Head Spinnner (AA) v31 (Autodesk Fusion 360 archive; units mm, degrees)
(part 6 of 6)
sketch "Seperator Shape" plane through (0, 0, 0) normal (1, 0, 0) x axis (0, 1, 0)
  line L1 (-26.9, 11.1645) -> (-26.9, 1.7)
  line L2 (-26.9, 13) -> (-26.9, 11.1645)
  line L3 (-26.9, 14.7) -> (-26.9, 13)
  line L4 (-26.9, 13) -> (-26.9, 14.7)
  line L5 (-26.9, 11.1645) -> (-26.9, 13)
  line L6 (-26.9, 1.7) -> (-26.9, 11.1645)
  line L7 (26.9, 1.7) -> (-26.9, 1.7)
  line L8 (-26.9, 1.7) -> (26.9, 1.7)
  line L9 (26.9, 11.1645) -> (26.9, 13)
  line L10 (26.9, 1.7) -> (26.9, 11.1645)
  line L11 (26.9, 11.1645) -> (26.9, 1.7)
  line L12 (26.9, 11.1645) -> (26.9, 13)
  line L13 (26.9, 14.7) -> (26.9, 13)
  line L14 (26.9, 13) -> (26.9, 14.7)
  line L15 (-19, 7.7) -> (-26.9, 14.7)
  line L16 (19, 7.7) -> (-19, 7.7)
  line L17 (26.9, 14.7) -> (19, 7.7)
  line L18 (0, 7.7) -> (0, 1.7)
  point P5 (-26.9, 14.7)
  point P12 (-26.9, 14.7)
  point P11 (26.9, 14.7)
  point P15 (26.9, 14.7)
  point P16 (0, 1.7)
  point P17 (0, 7.7)
  point P13 (-19, 7.7)
  point P14 (19, 7.7)
  coincident P5 P12
  perpendicular L3 L16
  coincident P11 P15
  equal L15 L17
  midpoint L8 P16
  midpoint L16 P17
  dimension "d17" distance L7 L16 = 6
  dimension "d18" distance P13 P14 = 38
extrude "Extrude3" new body sketch "Seperator Shape" profile of L1 L2 L3 L4 L5 L6 L7 L8 L9 L10 L11 L12 L13 L14 L15 L16 L17 distance 0.625 (= "( 1.25 / 2 ) * 1 mm")
copy_paste_bodies "CopyPasteBodies1"
move "Move1"
copy_paste_bodies "CopyPasteBodies2"
move "Move2"
combine "Combine1"
fillet "Fillet3" ChordLen 1.5
fillet "Fillet5" ChordLen 2.056
sketch "Mounting Holes" plane through (0, 0, 0) normal (0, 0, -1) x axis (1, 0, 0)
  curve K1 (28.8789, -27.5393) -> (29.9393, -26.4789)
  line L1 (29.9393, -26.4789) -> (29.9393, 26.4789)
  curve K2 (29.9393, 26.4789) -> (28.8789, 27.5393)
  line L2 (28.8789, 27.5393) -> (-28.8789, 27.5393)
  curve K3 (-28.8789, 27.5393) -> (-29.9393, 26.4789)
  line L3 (-29.9393, 26.4789) -> (-29.9393, -26.4789)
  curve K4 (-29.9393, -26.4789) -> (-28.8789, -27.5393)
  line L4 (-28.8789, -27.5393) -> (28.8789, -27.5393)
  line L5 (-15.9, -26.9) -> (-15.9, 26.9)
  line L6 (-29.3, -26.9) -> (-15.9, -26.9)
  line L7 (-29.3, 26.9) -> (-29.3, -26.9)
  line L8 (-15.9, 26.9) -> (-29.3, 26.9)
  line L9 (-14.65, 26.9) -> (-14.65, -26.9)
  line L10 (-0.625, 26.9) -> (-14.65, 26.9)
  line L11 (-0.625, -26.9) -> (-0.625, 26.9)
  line L12 (-14.65, -26.9) -> (-0.625, -26.9)
  line L13 (0.625, 26.9) -> (0.625, -26.9)
  line L14 (14.65, 26.9) -> (0.625, 26.9)
  line L15 (14.65, -26.9) -> (14.65, 26.9)
  line L16 (0.625, -26.9) -> (14.65, -26.9)
  line L17 (15.9, 26.9) -> (15.9, -26.9)
  line L18 (29.3, 26.9) -> (15.9, 26.9)
  line L19 (29.3, -26.9) -> (29.3, 26.9)
  line L20 (15.9, -26.9) -> (29.3, -26.9)
  line L21 (15.9, 0.053) -> (29.3, 0)
  line L22 (14.65, 0) -> (15.9, 0.053)
  line L23 (0.625, 0) -> (14.65, 0)
  line L24 (-29.3, 0) -> (-15.9, 0)
  line L25 (-0.625, 0) -> (0.625, 0)
  line L26 (-15.9, 0) -> (-14.65, 0)
  line L27 (-14.65, 0) -> (-0.625, 0)
  circle C1 centre (22.6, 0.0265) radius 1.5
  circle C2 centre (7.6375, 0) radius 1.5
  circle C3 centre (-7.6375, 0) radius 1.5
  circle C4 centre (-22.6, 0) radius 1.5
  point P26 (29.3, 0)
  point P27 (-29.3, 0)
  point P28 (15.9, 0.053)
  point P29 (14.65, 0)
  point P30 (0.625, 0)
  point P31 (-15.9, 0)
  point P32 (-0.625, 0)
  point P33 (-14.65, 0)
  point P34 (22.6, 0.0265)
  point P35 (7.6375, 0)
  point P36 (-7.6375, 0)
  point P37 (-22.6, 0)
  point P38 (22.6, 0.0265)
  point P39 (7.6375, 0)
  point P40 (-7.6375, 0)
  point P41 (-22.6, 0)
  midpoint L19 P26
  midpoint L7 P27
  coincident L17 P28
  coincident L15 P29
  coincident L13 P30
  coincident L5 P31
  coincident L11 P32
  coincident L9 P33
  midpoint L21 P34
  midpoint L23 P35
  midpoint L27 P36
  midpoint L24 P37
  horizontal L27
  horizontal L24
  horizontal L26
  horizontal L25
  horizontal L23
  coincident P34 P38
  coincident P35 P39
  coincident P36 P40
  coincident P37 P41
  equal C1 C2
  equal C2 C3
  equal C3 C4
  dimension "d29" diameter C1 = 3
extrude "Extrude4" cut sketch "Mounting Holes" profile of L27 C1 C2 C3 C4 against normal blind 26
chamfer "Chamfer2" distance 1.524
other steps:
base_feature "Base Feature1"
base_feature "Base Feature2"
named bodies: "battery box"

design "DC Motor Controller"
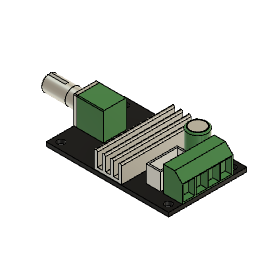
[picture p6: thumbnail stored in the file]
sketch "Sketch1" plane through (0, 0, 0) normal (0, 0, 1) x axis (1, 0, 0)
  line L1 (-25.0825, -16.0401) -> (25.0825, -16.0401)
  line L2 (-25.0825, 16.0401) -> (-25.0825, -16.0401)
  line L3 (25.0825, 16.0401) -> (-25.0825, 16.0401)
  line L4 (25.0825, -16.0401) -> (25.0825, 16.0401)
  line L5 (-25.0825, 16.0401) -> (25.0825, -16.0401)
  line L6 (25.0825, 16.0401) -> (-25.0825, -16.0401)
  line L7 (-12.9413, 4.7625) -> (-25.0825, 4.7625)
  line L8 (-12.9413, -4.7625) -> (-12.9413, 4.7625)
  line L9 (-25.0825, -4.7625) -> (-12.9413, -4.7625)
  line L10 (-25.0825, 4.7625) -> (-25.0825, -4.7625)
  line L11 (17.3355, 10.3822) -> (25.0825, 10.3822)
  line L12 (17.3355, -10.3823) -> (17.3355, 10.3822)
  line L13 (25.0825, -10.3823) -> (17.3355, -10.3823)
  line L14 (25.0825, 10.3822) -> (25.0825, -10.3823)
  line L15 (16.0655, 2.3177) -> (10.2235, 2.3177)
  line L16 (16.0655, -10.3822) -> (16.0655, 2.3177)
  line L17 (10.2235, -10.3823) -> (16.0655, -10.3822)
  line L18 (10.2235, 2.3177) -> (10.2235, -10.3823)
  line L19 (-5.6134, -15.875) -> (5.6134, -15.875)
  line L20 (-5.6134, 15.875) -> (-5.6134, -15.875)
  line L21 (5.6134, 15.875) -> (-5.6134, 15.875)
  line L22 (5.6134, -15.875) -> (5.6134, 15.875)
  line L23 (-5.6134, 15.875) -> (5.6134, -15.875)
  line L24 (5.6134, 15.875) -> (-5.6134, -15.875)
  line L25 (-25.0825, 0) -> (-12.9413, 0)
  line L26 (25.0825, 0) -> (17.3355, 0)
  line L27 (13.1445, -10.3822) -> (13.1445, 7.8422)
  line L28 (0, -27.94) -> (0, 0)
  line L29 (22.0345, 14.5415) -> (22.0345, 13.081)
  line L30 (22.352, 13.081) -> (22.0345, 13.081)
  line L31 (23.495, 13.081) -> (22.352, 13.081)
  circle C1 centre (22.0345, 13.081) radius 1.4605
  circle C2 centre (13.1445, 7.8422) radius 4.0195
  circle C3 centre (22.0345, -13.081) radius 1.4605
  circle C4 centre (-22.0345, 13.081) radius 1.4605
  circle C5 centre (-22.0345, -13.081) radius 1.4605
  point P6 (0, 0)
  point P1 (0, 0)
  point P7 (-25.0825, 4.7625)
  point P11 (25.0825, 10.3822)
  point P25 (0, 0)
  point P26 (-12.9413, 0)
  point P27 (-25.0825, 0)
  point P28 (17.3355, 0)
  point P29 (25.0825, 0)
  point P20 (13.1445, 7.8422)
  point P30 (13.1445, 7.8422)
  point P31 (13.1445, -10.3822)
  point P32 (0, 0)
  point P15 (22.0345, 13.081)
  point P34 (22.0345, 13.081)
  point P35 (22.0345, 14.5415)
  point P36 (22.0345, 13.081)
  point P38 (23.495, 13.081)
  point P4 (-25.0825, 16.0401)
  point P5 (25.0825, 16.0401)
  point P3 (-25.0825, -16.0401)
  point P8 (-12.9413, 4.7625)
  point P9 (-12.9413, -4.7625)
  point P10 (-25.0825, -4.7625)
  point P21 (5.6134, -15.875)
  point P22 (-5.6134, -15.875)
  point P24 (5.6134, 15.875)
  point P12 (17.3355, 10.3822)
  point P13 (17.3355, -10.3823)
  point P14 (25.0825, -10.3823)
  point P16 (10.2235, 2.3177)
  point P19 (10.2235, -10.3823)
  point P18 (16.0655, -10.3822)
  horizontal L1
  perpendicular L1 L2
  parallel L1 L3
  parallel L2 L4
  coincident L5 P6
  coincident L6 P6
  coincident P1 P6
  horizontal L7
  vertical L8
  horizontal L9
  vertical L10
  coincident L2 P7
  horizontal L11
  vertical L12
  horizontal L13
  vertical L14
  coincident L4 P11
  horizontal L15
  vertical L16
  horizontal L17
  vertical L18
  horizontal L19
  perpendicular L19 L20
  parallel L19 L21
  parallel L20 L22
  coincident L23 P25
  coincident L24 P25
  coincident P1 P25
  midpoint L8 P26
  midpoint L10 P27
  midpoint L2 P27
  midpoint L12 P28
  coincident L14 P29
  horizontal L26
  midpoint L4 P29
  collinear L13 L17
  coincident P20 P30
  midpoint L17 P31
  vertical L27
  coincident P25 P32
  perpendicular L19 L28
  coincident P15 P34
  coincident C1 P35
  vertical L29
  coincident P15 P36
  perpendicular L29 L30
  coincident C1 P38
  perpendicular L29 L31
  symmetric C1 L26 C3
  symmetric C1 L28 C4
  symmetric L28 C3 C5
  dimension "d1" distance P4 P5 = 50.165
  dimension "d2" distance P3 P4 = 32.0802
  dimension "d3" distance P8 P9 = 9.525
  dimension "d4" distance P9 P10 = 12.1412
  dimension "d5" distance P21 P22 = 11.2268
  dimension "d6" distance P21 P24 = 31.75
  dimension "d7" distance P12 P13 = 20.7645
  dimension "d8" distance P13 P14 = 7.747
  dimension "d9" distance P16 P19 = 12.7
  dimension "d10" distance P18 P19 = 5.842
  dimension "d11" diameter C2 = 8.0391
  dimension "d12" distance L11 P20 = 2.54
  dimension "d13" distance L12 L16 = 1.27
  dimension "d16" distance L3 P35 = 1.4986
  dimension "d17" distance L4 P38 = 1.5875
  dimension "d18" diameter C1 = 2.921
extrude "Extrude1" new body sketch "Sketch1" profile of L1 L2 L3 L4 L7 L8 L9 L10 L11 L12 L13 L14 C1 L15 L16 L17 L18 C2 L19 L20 L21 L22 C3 C4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 against normal blind 1.6002
extrude "Extrude2" new body sketch "Sketch1" profile of L2 L7 L8 L9 L10 along normal blind 11.4046
extrude "Extrude3" new body sketch "Sketch1" profile of L19 L20 L21 L22 along normal blind 7.3152
extrude "Extrude4" new body sketch "Sketch1" profile of L15 L16 L17 L18 along normal blind 7.0485
extrude "Extrude5" new body sketch "Sketch1" profile of C2 along normal blind 12.827
extrude "Extrude6" new body sketch "Sketch1" profile of L4 L11 L12 L13 L14 along normal blind 10.4013
sketch "Sketch2" plane through (0, -15.875, 0) normal (0, -1, 0) x axis (1, 0, 0)
  line L1 (5.6134, 0) -> (-5.6134, 0)
  line L2 (5.6134, 7.3152) -> (5.6134, 0)
  line L3 (-5.6134, 7.3152) -> (5.6134, 7.3152)
  line L4 (-5.6134, 0) -> (-5.6134, 7.3152)
  line L5 (0.9525, 7.3152) -> (-0.9525, 7.3152)
  line L6 (0.9525, 1.27) -> (0.9525, 7.3152)
  line L7 (-0.9525, 1.27) -> (0.9525, 1.27)
  line L8 (-0.9525, 7.3152) -> (-0.9525, 1.27)
  line L9 (0, 0) -> (0, 1.27)
  line L10 (-2.3495, 1.27) -> (-2.3495, 7.3152)
  line L11 (-4.2545, 7.3152) -> (-4.2545, 1.27)
  line L12 (-4.2545, 1.27) -> (-2.3495, 1.27)
  line L13 (4.2545, 1.27) -> (4.2545, 7.3152)
  line L14 (2.3495, 7.3152) -> (2.3495, 1.27)
  line L15 (2.3495, 1.27) -> (4.2545, 1.27)
  point P6 (-0.9525, 7.3152)
  point P10 (0, 1.27)
  point P1 (0, 0)
  point P11 (0, 0)
  point P8 (0.9525, 1.27)
  point P9 (-0.9525, 1.27)
  horizontal L5
  vertical L6
  horizontal L7
  vertical L8
  coincident L3 P6
  midpoint L7 P10
  coincident P1 P11
  vertical L9
  dimension "d31" distance P8 P9 = 1.905
  dimension "d33" distance L1 L7 = 1.27
  dimension "d36" R-Pattern1-uDistance = 3.302
  dimension "d37" R-Pattern1-vDistance = 0
extrude "Extrude7" cut sketch "Sketch2" profile of L3 L5 L6 L7 L8 L10 L11 L12 L13 L14 L15 against normal blind 38.1
fillet "Fillet1" sketch "Sketch2" radius 0.635
fillet "Fillet2" sketch "Sketch2" radius 0.635
chamfer "Chamfer1" distance 3.175
shell "Shell1" innerThickness 0.635
sketch "Sketch3" plane through (25.0825, 0, 0) normal (1, 0, 0) x axis (0, 1, 0)
  line L1 (-10.3823, 7.2263) -> (10.3822, 7.2263)
  line L2 (-10.3823, 0) -> (-10.3823, 7.2263)
  line L3 (10.3822, 0) -> (-10.3823, 0)
  line L4 (10.3822, 7.2263) -> (10.3822, 0)
  line L5 (-5.3023, 6.985) -> (-9.7473, 6.985)
  line L6 (-5.3023, 0.635) -> (-5.3023, 6.985)
  line L7 (-9.7473, 0.635) -> (-5.3023, 0.635)
  line L8 (-9.7473, 6.985) -> (-9.7473, 0.635)
  line L9 (-4.7519, 6.985) -> (-4.7519, 0.635)
  line L10 (-0.3069, 6.985) -> (-4.7519, 6.985)
  line L11 (-0.3069, 0.635) -> (-0.3069, 6.985)
  line L12 (-4.7519, 0.635) -> (-0.3069, 0.635)
  line L13 (0.2434, 6.985) -> (0.2434, 0.635)
  line L14 (4.6884, 6.985) -> (0.2434, 6.985)
  line L15 (4.6884, 0.635) -> (4.6884, 6.985)
  line L16 (0.2434, 0.635) -> (4.6884, 0.635)
  line L17 (5.2387, 6.985) -> (5.2387, 0.635)
  line L18 (9.6837, 6.985) -> (5.2387, 6.985)
  line L19 (9.6837, 0.635) -> (9.6837, 6.985)
  line L20 (5.2387, 0.635) -> (9.6837, 0.635)
  point P7 (-5.3023, 6.985)
  point P8 (-5.3023, 0.635)
  point P9 (-9.7473, 0.635)
  horizontal L5
  vertical L6
  horizontal L7
  vertical L8
  dimension "d46" distance P7 P8 = 6.35
  dimension "d47" distance P8 P9 = 4.445
  dimension "d48" distance L2 L8 = 0.635
  dimension "d49" distance L3 L7 = 0.635
  dimension "d52" R-Pattern1-uDistance = 14.986
  dimension "d53" R-Pattern1-vDistance = 0
extrude "Extrude8" cut sketch "Sketch3" profile of L5 L6 L7 L8 L9 L10 L11 L12 L13 L14 L15 L16 L17 L18 L19 L20 against normal blind 2.54
sketch "Sketch4" plane through (-25.0825, 0, 0) normal (-1, 0, 0) x axis (0, -1, 0)
  line L1 (4.7625, 0) -> (-4.7625, 0)
  line L2 (4.7625, 11.4046) -> (4.7625, 0)
  line L3 (-4.7625, 11.4046) -> (4.7625, 11.4046)
  line L4 (-4.7625, 0) -> (-4.7625, 11.4046)
  line L5 (0, 11.4046) -> (0, 0)
  circle C1 centre (0, 5.7023) radius 3.3655
  point P1 (0, 0)
  point P6 (0, 0)
  point P7 (0, 11.4046)
  point P8 (0, 5.7023)
  point P9 (0, 5.7023)
  coincident P1 P6
  midpoint L3 P7
  midpoint L5 P8
  coincident P8 P9
  dimension "d56" diameter C1 = 6.731
extrude "Extrude9" add sketch "Sketch4" profile of C1 along normal blind 15.24
sketch "Sketch5" plane through (-40.3225, 0, 0) normal (-1, 0, 0) x axis (0, -1, 0)
  circle C1 centre (0, 5.7023) radius 3.3655
  circle C2 centre (0, 5.7023) radius 3.2702
  dimension "d59" = -0.0953
extrude "Extrude10" cut sketch "Sketch5" against normal blind 10.2235
fillet "Fillet3" sketch "Sketch2" radius 0.635
sketch "Sketch6" plane through (-40.3225, 0, 0) normal (-1, 0, 0) x axis (0, -1, 0)
  line L1 (-0.635, 1.8923) -> (0.635, 1.8923)
  line L2 (-0.635, 9.5123) -> (-0.635, 1.8923)
  line L3 (0.635, 9.5123) -> (-0.635, 9.5123)
  line L4 (0.635, 1.8923) -> (0.635, 9.5123)
  line L5 (-0.635, 9.5123) -> (0.635, 1.8923)
  line L6 (0.635, 9.5123) -> (-0.635, 1.8923)
  circle C1 centre (0, 5.7023) radius 2.6353
  point P7 (0, 5.7023)
  point P2 (0, 5.7023)
  point P3 (0.635, 1.8923)
  point P4 (-0.635, 1.8923)
  point P6 (0.635, 9.5123)
  horizontal L1
  perpendicular L1 L2
  parallel L1 L3
  parallel L2 L4
  coincident L5 P7
  coincident L6 P7
  coincident P2 P7
  dimension "d64" distance P3 P4 = 1.27
  dimension "d65" distance P3 P6 = 7.62
extrude "Extrude11" cut sketch "Sketch6" profile of C1 L1 L2 L3 L4 against normal blind 7.62
fillet "Fillet4" sketch "Sketch2" radius 0.3175
sketch "Sketch7" plane through (0, 0, 11.4046) normal (0, 0, 1) x axis (-1, 0, 0)
  line L1 (25.0825, -4.445) -> (12.9413, -4.445)
  line L2 (25.0825, 4.445) -> (25.0825, -4.445)
  line L3 (12.9413, 4.445) -> (25.0825, 4.445)
  line L4 (12.9413, -4.445) -> (12.9413, 4.445)
  line L5 (23.8125, 4.445) -> (23.8125, 0)
  point P7 (23.8125, 4.445)
  coincident L3 P7
  perpendicular L3 L5
  dimension "d70" distance L2 L5 = 1.27
split "Split1"
boundary_fill "BoundaryFill1"
shell "Shell2" innerThickness 0.3175
sketch "Sketch8" plane through (0, 0, 12.827) normal (0, 0, 1) x axis (-1, 0, 0)
  circle C1 centre (-13.1445, -7.8422) radius 3.3846
  circle C2 centre (-13.1445, -7.8422) radius 3.175
  concentric C1 C2
  dimension "d72" diameter C2 = 6.35
extrude "Extrude12" cut sketch "Sketch8" profile of C2 against normal blind 8.89
offset_faces "OffsetFaces1" distance -0.3175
